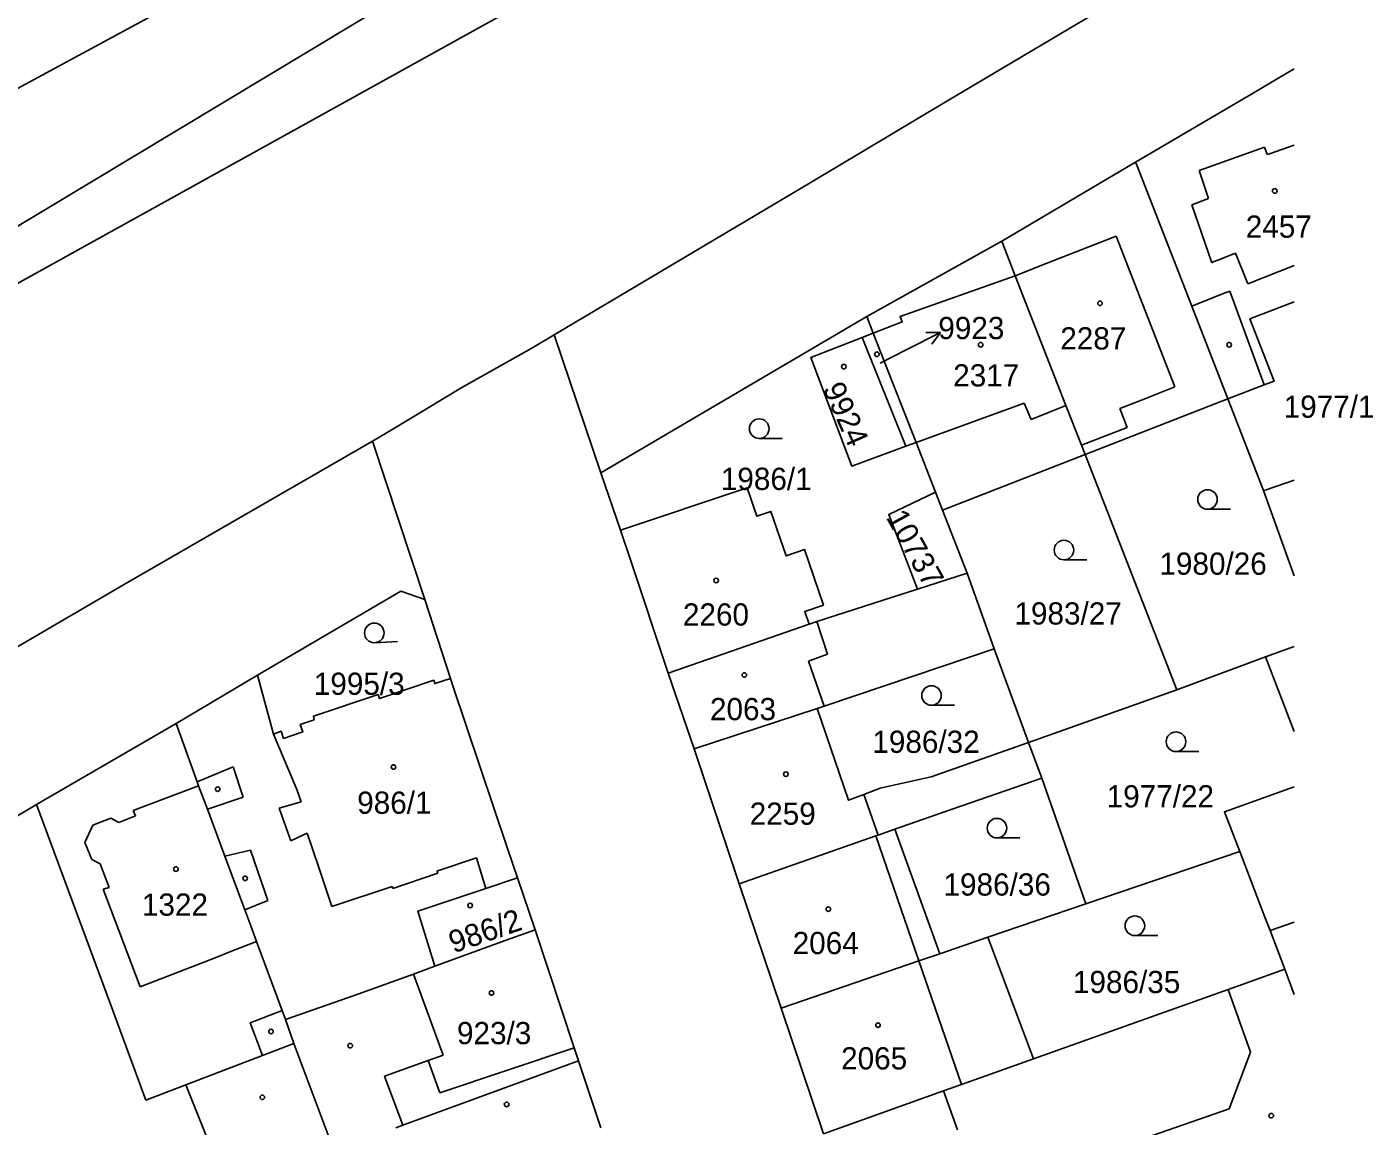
# Model space of a CAD drawing. Extents: x -564952 to -564307, y -1202373 to -1201847.
# Drawn here: x -564411.7 to -564308.6, y -1202022 to -1201937.9 of the extents above; entities that cross this region are included whole.
import ezdxf

# ---------------------------------------------------------------- set-up
doc = ezdxf.new("R2010")
doc.units = 0
for name, color, linetype in [('Hranice parcel', 7, 'Continuous'), ('Parcelní čísla', 7, 'Continuous'), ('Pop  PČ popisy', 7, 'Continuous'), ('Vnitřní kresba', 7, 'Continuous'), ('Značky budov', 7, 'Continuous'), ('Značky kultur', 7, 'Continuous')]:
    doc.layers.add(name, color=color, linetype=linetype)

msp = doc.modelspace()

# ---------------------------------------------------------------- linework, layer by layer
at = {"layer": 'Hranice parcel'}
for p, q in [((-564337.02, -1201954.3), (-564326.78, -1201948.25)), ((-564351.71, -1201949.82), (-564371.3, -1201961.47)), ((-564347.36, -1201960.07), (-564337.02, -1201954.3)), ((-564337.02, -1201954.3), (-564336, -1201956.94)), ((-564347.36, -1201960.07), (-564367.72, -1201972.02)), ((-564346.87, -1201961.33), (-564347.36, -1201960.07)), ((-564371.3, -1201961.47), (-564373.01, -1201962.49)), ((-564371.3, -1201961.47), (-564367.72, -1201972.02)), ((-564347.71, -1201961.66), (-564346.87, -1201961.33)), ((-564344.37, -1201969.99), (-564347.71, -1201961.66)), ((-564346.87, -1201961.33), (-564343.59, -1201969.71)), ((-564319.72, -1201966.37), (-564330.65, -1201970.63)), ((-564319.72, -1201966.37), (-564316.98, -1201973.38)), ((-564383.64, -1201968.69), (-564385.2, -1201969.59)), ((-564385.2, -1201969.59), (-564403.97, -1201980.4)), ((-564385.2, -1201969.59), (-564381.2, -1201981.72)), ((-564343.59, -1201969.71), (-564344.37, -1201969.99)), ((-564342.11, -1201973.51), (-564343.59, -1201969.71)), ((-564330.65, -1201970.63), (-564341.57, -1201974.89)), ((-564330.65, -1201970.63), (-564323.63, -1201988.62)), ((-564367.72, -1201972.02), (-564366.23, -1201976.42)), ((-564342.11, -1201973.51), (-564341.57, -1201974.89)), ((-564314.65, -1201979.9), (-564316.98, -1201973.38)), ((-564341.57, -1201974.89), (-564339.69, -1201979.71)), ((-564403.97, -1201980.4), (-564468.28, -1202018.06)), ((-564339.69, -1201979.71), (-564343.48, -1201980.92)), ((-564339.69, -1201979.71), (-564337.62, -1201985.49)), ((-564345.4, -1201981.54), (-564343.48, -1201980.92)), ((-564381.2, -1201981.72), (-564379.24, -1201987.75)), ((-564351.2, -1201983.4), (-564345.4, -1201981.54)), ((-564351.78, -1201983.6), (-564351.2, -1201983.4)), ((-564351.78, -1201983.6), (-564362.57, -1201987.36)), ((-564337.62, -1201985.49), (-564334.98, -1201992.65)), ((-564316.83, -1201986.11), (-564314.65, -1201985.31)), ((-564316.83, -1201986.11), (-564323.63, -1201988.62)), ((-564314.65, -1201991.82), (-564316.83, -1201986.11)), ((-564400.25, -1201991.19), (-564394, -1201987.51)), ((-564360.58, -1201993.14), (-564362.57, -1201987.36)), ((-564323.63, -1201988.62), (-564334.98, -1201992.65)), ((-564360.58, -1201993.14), (-564351.17, -1201990.05)), ((-564410.93, -1201997.4), (-564400.25, -1201991.19)), ((-564334.98, -1201992.65), (-564333.97, -1201995.38)), ((-564357.13, -1202003.48), (-564360.58, -1201993.14)), ((-564333.97, -1201995.38), (-564330.59, -1202004.99)), ((-564427.05, -1202006.92), (-564410.93, -1201997.4)), ((-564346.5, -1201999.74), (-564345.23, -1201999.29)), ((-564345.23, -1201999.29), (-564341.76, -1202008.82)), ((-564330.59, -1202004.99), (-564318.8, -1202001)), ((-564374.1, -1202003.01), (-564372.76, -1202006.98)), ((-564353.91, -1202012.99), (-564357.13, -1202003.48)), ((-564338.1, -1202007.56), (-564330.59, -1202004.99)), ((-564372.76, -1202006.98), (-564369.76, -1202016.02)), ((-564315.35, -1202010), (-564316.49, -1202007.04)), ((-564341.76, -1202008.82), (-564338.1, -1202007.56)), ((-564334.61, -1202016.87), (-564338.1, -1202007.56)), ((-564314.65, -1202011.93), (-564315.35, -1202010)), ((-564386.61, -1202012.01), (-564391.87, -1202013.85)), ((-564350.68, -1202022.6), (-564353.91, -1202012.99)), ((-564391.22, -1202015.7), (-564391.87, -1202013.85)), ((-564393.62, -1202016.61), (-564391.22, -1202015.7)), ((-564388.33, -1202023.43), (-564391.22, -1202015.7)), ((-564369.76, -1202016.02), (-564369.43, -1202017.02)), ((-564369.43, -1202017.02), (-564367.73, -1202022.14))]:
    msp.add_line(p, q, dxfattribs=at)
for points in [[(-564428.74, -1201951.43), (-564393.56, -1201932.42), (-564314.65, -1201888.26)], [(-564479.51, -1201991.57), (-564446.91, -1201976.65), (-564359.6, -1201928.27)], [(-564314.65, -1201928.08), (-564320.77, -1201931.52), (-564331.09, -1201937.56), (-564341.36, -1201943.65), (-564351.71, -1201949.82)], [(-564479.51, -1201991.57), (-564464.1, -1201982.45), (-564434.29, -1201966.3), (-564383.08, -1201935.53)], [(-564326.78, -1201948.25), (-564318.27, -1201943.24), (-564318.1, -1201943.14), (-564315.26, -1201941.47), (-564315.07, -1201941.36), (-564314.65, -1201941.11)], [(-564319.72, -1201966.37), (-564322.49, -1201959.27), (-564326.69, -1201948.48), (-564326.78, -1201948.25)], [(-564336, -1201956.94), (-564332.12, -1201966.88), (-564330.93, -1201969.91), (-564330.65, -1201970.63)], [(-564314.65, -1201958.93), (-564318.03, -1201960.24), (-564316.18, -1201965), (-564316.95, -1201965.3), (-564319.72, -1201966.37)], [(-564344.37, -1201969.99), (-564348.52, -1201971.51), (-564351.66, -1201963.19), (-564347.71, -1201961.66)], [(-564373.01, -1201962.49), (-564378.36, -1201965.49), (-564383.64, -1201968.69)], [(-564366.23, -1201976.42), (-564356.52, -1201973.17), (-564355.79, -1201975.34), (-564354.7, -1201974.97), (-564353.55, -1201978.36), (-564352.14, -1201977.88), (-564350.69, -1201982.14), (-564352.11, -1201982.62), (-564351.78, -1201983.6)], [(-564316.98, -1201973.38), (-564316.79, -1201973.32), (-564314.65, -1201972.59)], [(-564343.48, -1201980.92), (-564345.68, -1201975.21), (-564342.11, -1201973.51)], [(-564362.57, -1201987.36), (-564365.49, -1201978.59), (-564366.23, -1201976.42)], [(-564394, -1201987.51), (-564383.04, -1201981.07), (-564381.2, -1201981.72)], [(-564351.17, -1201990.05), (-564350.64, -1201989.88), (-564343.75, -1201987.56), (-564337.62, -1201985.49)], [(-564394, -1201987.51), (-564392.78, -1201992.02), (-564392.21, -1201991.79), (-564392.02, -1201992.34), (-564390.54, -1201991.85), (-564390.74, -1201991.28), (-564389.68, -1201990.92), (-564389.73, -1201990.63), (-564384.78, -1201988.99), (-564384.68, -1201989.29), (-564380.52, -1201987.89), (-564380.44, -1201988.15), (-564379.24, -1201987.75)], [(-564379.24, -1201987.75), (-564379.05, -1201988.32), (-564374.89, -1202000.68), (-564374.1, -1202003.01)], [(-564334.98, -1201992.65), (-564342.43, -1201995.27), (-564346.34, -1201996.15), (-564347.59, -1201996.63), (-564348.76, -1201997.08), (-564351.17, -1201990.05)], [(-564391.87, -1202013.85), (-564392.13, -1202013.15), (-564394.08, -1202007.89), (-564394.53, -1202006.69), (-564394.99, -1202005.45), (-564396.51, -1202001.36), (-564397.85, -1201997.76), (-564398.52, -1201995.97), (-564398.63, -1201995.67), (-564400.25, -1201991.19)], [(-564333.97, -1201995.38), (-564341.49, -1201997.99), (-564345.23, -1201999.29)], [(-564318.8, -1202001), (-564319.16, -1202000.08), (-564319.98, -1201997.97), (-564314.65, -1201996.04)], [(-564410.93, -1201997.4), (-564405.27, -1202012.69), (-564402.56, -1202020.02)], [(-564357.13, -1202003.48), (-564346.66, -1201999.8), (-564346.5, -1201999.74)], [(-564316.49, -1202007.04), (-564316.88, -1202006.02), (-564318.8, -1202001)], [(-564380.43, -1202009.77), (-564381.74, -1202005.57), (-564376.54, -1202003.83), (-564374.1, -1202003.01)], [(-564372.76, -1202006.98), (-564375.32, -1202007.91), (-564380.43, -1202009.77)], [(-564314.65, -1202006.41), (-564316.49, -1202007.04)], [(-564341.76, -1202008.82), (-564343.37, -1202009.37), (-564353.91, -1202012.99)], [(-564380.43, -1202009.77), (-564382.06, -1202010.37), (-564386.61, -1202012.01)], [(-564315.35, -1202010), (-564318.2, -1202011.02), (-564319.71, -1202011.56), (-564334.61, -1202016.87)], [(-564402.56, -1202020.02), (-564399.49, -1202018.85), (-564393.62, -1202016.61)], [(-564369.43, -1202017.02), (-564382.88, -1202021.93), (-564383.43, -1202022.13)], [(-564334.61, -1202016.87), (-564340.12, -1202018.83), (-564341.48, -1202019.32), (-564350.68, -1202022.6)]]:
    msp.add_lwpolyline(points, dxfattribs=at)
at = {"layer": 'Pop  PČ popisy'}
for p, q in [((-564344.39, -1201962.64), (-564341.72, -1201961.28)), ((-564341.72, -1201961.28), (-564342.84, -1201961.29)), ((-564341.72, -1201961.28), (-564342.38, -1201962.18)), ((-564346.35, -1201963.63), (-564344.39, -1201962.64))]:
    msp.add_line(p, q, dxfattribs=at)
at = {"layer": 'Vnitřní kresba'}
for p, q in [((-564316.92, -1201947.1), (-564321.92, -1201948.89)), ((-564316.72, -1201947.67), (-564316.92, -1201947.1)), ((-564316.53, -1201947.6), (-564314.65, -1201946.94)), ((-564316.72, -1201947.67), (-564316.53, -1201947.6)), ((-564321.92, -1201948.89), (-564321.49, -1201950.18)), ((-564321.49, -1201950.18), (-564321.2, -1201951.04)), ((-564321.2, -1201951.04), (-564322.47, -1201951.52)), ((-564320.96, -1201955.94), (-564322.47, -1201951.52)), ((-564328.27, -1201953.92), (-564334.09, -1201956.19)), ((-564328.27, -1201953.92), (-564323.78, -1201965.45)), ((-564320.5, -1201955.75), (-564319.13, -1201955.2)), ((-564319.13, -1201955.2), (-564318.19, -1201957.56)), ((-564334.09, -1201956.19), (-564335.8, -1201956.86)), ((-564320.85, -1201955.88), (-564320.96, -1201955.94)), ((-564320.85, -1201955.88), (-564320.5, -1201955.75)), ((-564314.65, -1201956.16), (-564318.19, -1201957.56)), ((-564335.8, -1201956.86), (-564336, -1201956.94)), ((-564322.04, -1201959.09), (-564319.92, -1201958.25)), ((-564319.57, -1201958.11), (-564319.92, -1201958.25)), ((-564316.95, -1201965.3), (-564319.57, -1201958.11)), ((-564322.49, -1201959.27), (-564322.04, -1201959.09)), ((-564326.32, -1201966.45), (-564323.78, -1201965.45)), ((-564335.31, -1201966.68), (-564343.59, -1201969.71)), ((-564334.88, -1201967.71), (-564335.31, -1201966.68)), ((-564332.12, -1201966.88), (-564334.78, -1201967.95)), ((-564328, -1201967.11), (-564326.32, -1201966.45)), ((-564334.78, -1201967.95), (-564334.88, -1201967.71)), ((-564328, -1201967.11), (-564327.44, -1201968.55)), ((-564327.44, -1201968.55), (-564330.93, -1201969.91)), ((-564351.2, -1201983.4), (-564350.37, -1201985.9)), ((-564350.37, -1201985.9), (-564351.84, -1201986.43)), ((-564351.84, -1201986.43), (-564350.64, -1201989.88)), ((-564390.99, -1201996.24), (-564392.78, -1201992.02)), ((-564398.63, -1201995.67), (-564395.88, -1201994.52)), ((-564395.88, -1201994.52), (-564395.1, -1201996.84)), ((-564398.52, -1201995.97), (-564403.54, -1201997.87)), ((-564395.1, -1201996.84), (-564397.85, -1201997.76)), ((-564390.67, -1201997.19), (-564390.99, -1201996.24)), ((-564347.59, -1201996.63), (-564346.5, -1201999.74)), ((-564403.54, -1201997.87), (-564403.36, -1201998.26)), ((-564390.67, -1201997.19), (-564392.36, -1201997.69)), ((-564391.47, -1202000.18), (-564392.36, -1201997.69)), ((-564406.63, -1201998.97), (-564407.23, -1202000.31)), ((-564405.24, -1201998.44), (-564406.63, -1201998.97)), ((-564404.62, -1201998.78), (-564405.24, -1201998.44)), ((-564403.36, -1201998.26), (-564404.62, -1201998.78)), ((-564391.47, -1202000.18), (-564390.2, -1201999.6)), ((-564390.2, -1201999.6), (-564389.29, -1202002.3)), ((-564346.66, -1201999.8), (-564343.37, -1202009.37)), ((-564407.23, -1202000.31), (-564406.69, -1202001.62)), ((-564394.56, -1202000.9), (-564396.51, -1202001.36)), ((-564394.56, -1202000.9), (-564393.21, -1202004.74)), ((-564406.69, -1202001.62), (-564406.05, -1202001.95)), ((-564406.05, -1202001.95), (-564405.37, -1202003.74)), ((-564377.25, -1202001.48), (-564380.27, -1202002.51)), ((-564377.25, -1202001.48), (-564376.54, -1202003.83)), ((-564389.29, -1202002.3), (-564388.32, -1202005.2)), ((-564380.21, -1202002.66), (-564383.65, -1202003.83)), ((-564380.27, -1202002.51), (-564380.21, -1202002.66)), ((-564405.37, -1202003.74), (-564405.84, -1202003.87)), ((-564404.63, -1202007.05), (-564405.84, -1202003.87)), ((-564383.7, -1202003.68), (-564388.32, -1202005.2)), ((-564383.65, -1202003.83), (-564383.7, -1202003.68)), ((-564393.21, -1202004.74), (-564394.99, -1202005.45)), ((-564404.63, -1202007.05), (-564402.99, -1202011.34)), ((-564396.12, -1202008.68), (-564394.08, -1202007.89)), ((-564402.99, -1202011.34), (-564397.26, -1202009.13)), ((-564397.26, -1202009.13), (-564396.12, -1202008.68)), ((-564343.37, -1202009.37), (-564340.12, -1202018.83)), ((-564379.81, -1202016.57), (-564382.06, -1202010.37)), ((-564319.71, -1202011.56), (-564318, -1202016.36)), ((-564394.57, -1202014.11), (-564392.13, -1202013.15)), ((-564394.57, -1202014.11), (-564393.62, -1202016.61)), ((-564369.76, -1202016.02), (-564380.05, -1202019.46)), ((-564319.62, -1202020.68), (-564318, -1202016.36)), ((-564384.29, -1202018.19), (-564380.94, -1202016.98)), ((-564380.94, -1202016.98), (-564379.81, -1202016.57)), ((-564380.05, -1202019.46), (-564380.94, -1202016.98)), ((-564384.29, -1202018.19), (-564382.88, -1202021.93)), ((-564399.49, -1202018.85), (-564396.18, -1202027.14)), ((-564341.48, -1202019.32), (-564340.42, -1202022.3)), ((-564319.62, -1202020.68), (-564335.3, -1202026.12))]:
    msp.add_line(p, q, dxfattribs=at)
msp.add_lwpolyline([(-564336, -1201956.94), (-564344.81, -1201960.05), (-564344.65, -1201960.47), (-564346.87, -1201961.33)], dxfattribs=at)
at = {"layer": 'Značky budov'}
for centre in [(-564316.13, -1201950.45), (-564329.51, -1201959.05), (-564346.59, -1201962.95), (-564338.65, -1201962.22), (-564319.62, -1201962.22), (-564349.12, -1201963.89), (-564358.9, -1201980.26), (-564356.74, -1201987.49), (-564383.6, -1201994.53), (-564353.56, -1201995.08), (-564397.06, -1201996.23), (-564400.26, -1202002.34), (-564394.96, -1202003.05), (-564377.73, -1202005.13), (-564350.31, -1202005.41), (-564376.1, -1202011.82), (-564346.51, -1202014.28), (-564392.98, -1202014.77), (-564386.91, -1202015.85), (-564393.64, -1202019.81), (-564374.94, -1202020.35), (-564316.4, -1202021.21)]:
    msp.add_circle(centre, 0.175, dxfattribs=at)
at = {"layer": 'Značky kultur'}
for p, q in [((-564355.6, -1201969.39), (-564353.85, -1201969.39)), ((-564321.28, -1201974.81), (-564319.53, -1201974.81)), ((-564332.27, -1201978.68), (-564330.52, -1201978.68)), ((-564385.03, -1201985.02), (-564383.29, -1201984.93)), ((-564342.41, -1201989.81), (-564340.66, -1201989.81)), ((-564323.69, -1201993.35), (-564321.94, -1201993.35)), ((-564337.4, -1201999.96), (-564335.65, -1201999.96)), ((-564326.84, -1202007.43), (-564325.09, -1202007.43))]:
    msp.add_line(p, q, dxfattribs=at)
for centre in [(-564355.6, -1201968.64), (-564321.28, -1201974.06), (-564332.27, -1201977.93), (-564385.07, -1201984.27), (-564342.41, -1201989.06), (-564323.69, -1201992.6), (-564337.4, -1201999.21), (-564326.84, -1202006.68)]:
    msp.add_circle(centre, 0.75, dxfattribs=at)

# ---------------------------------------------------------------- texts
at = {"layer": 'Parcelní čísla'}
for s, p in [('2457', (-564318.35, -1201954.03)), ('9923', (-564341.89, -1201961.79)), ('2287', (-564332.55, -1201962.58)), ('2317', (-564340.75, -1201965.41)), ('1977/1', (-564315.45, -1201967.81)), ('1986/1', (-564358.54, -1201973.33)), ('1980/26', (-564324.96, -1201979.82)), ('2260', (-564361.44, -1201983.71)), ('1983/27', (-564336.06, -1201983.63)), ('1995/3', (-564389.7, -1201989.01)), ('2063', (-564359.37, -1201990.95)), ('1986/32', (-564346.94, -1201993.45)), ('1977/22', (-564329, -1201997.62)), ('986/1', (-564386.38, -1201998.11)), ('2259', (-564356.33, -1201998.95)), ('1986/36', (-564341.49, -1202004.37)), ('1322', (-564402.86, -1202005.91)), ('2064', (-564353.04, -1202008.85)), ('1986/35', (-564331.58, -1202011.83)), ('923/3', (-564378.74, -1202015.74)), ('2065', (-564349.33, -1202017.67))]:
    msp.add_text(s, height=1.7, dxfattribs=at).set_placement(p)
for s, rotation, p in [('9924', 294, (-564350.77, -1201965.55)), ('10737', 299, (-564345.93, -1201975.42)), ('986/2', 19, (-564379.01, -1202008.8))]:
    msp.add_text(s, height=1.7, rotation=rotation, dxfattribs=at).set_placement(p)

doc.saveas('drawing.dxf')
